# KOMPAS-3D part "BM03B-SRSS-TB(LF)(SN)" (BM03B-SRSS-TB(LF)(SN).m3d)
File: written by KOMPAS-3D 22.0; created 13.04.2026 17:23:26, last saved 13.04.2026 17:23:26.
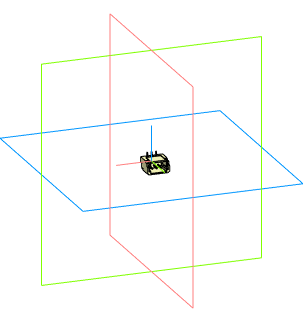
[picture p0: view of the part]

Document properties: Автор: Andrey; Полное имя файла: C:\Users\User1\Documents\BM03B-SRSS-TB(LF)(SN).m3d

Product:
- Part/product: BM03B-SRSS-TB(LF)(SN)

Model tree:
1. Операция без истории:1
2. Операция без истории:2
3. Операция без истории:3
4. Операция без истории:4
5. Операция без истории:5
6. Операция без истории:6
7. Операция без истории:7
8. Операция без истории:8
9. Операция без истории:9
10. Операция без истории:10
11. Операция без истории:11
12. Операция без истории:12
